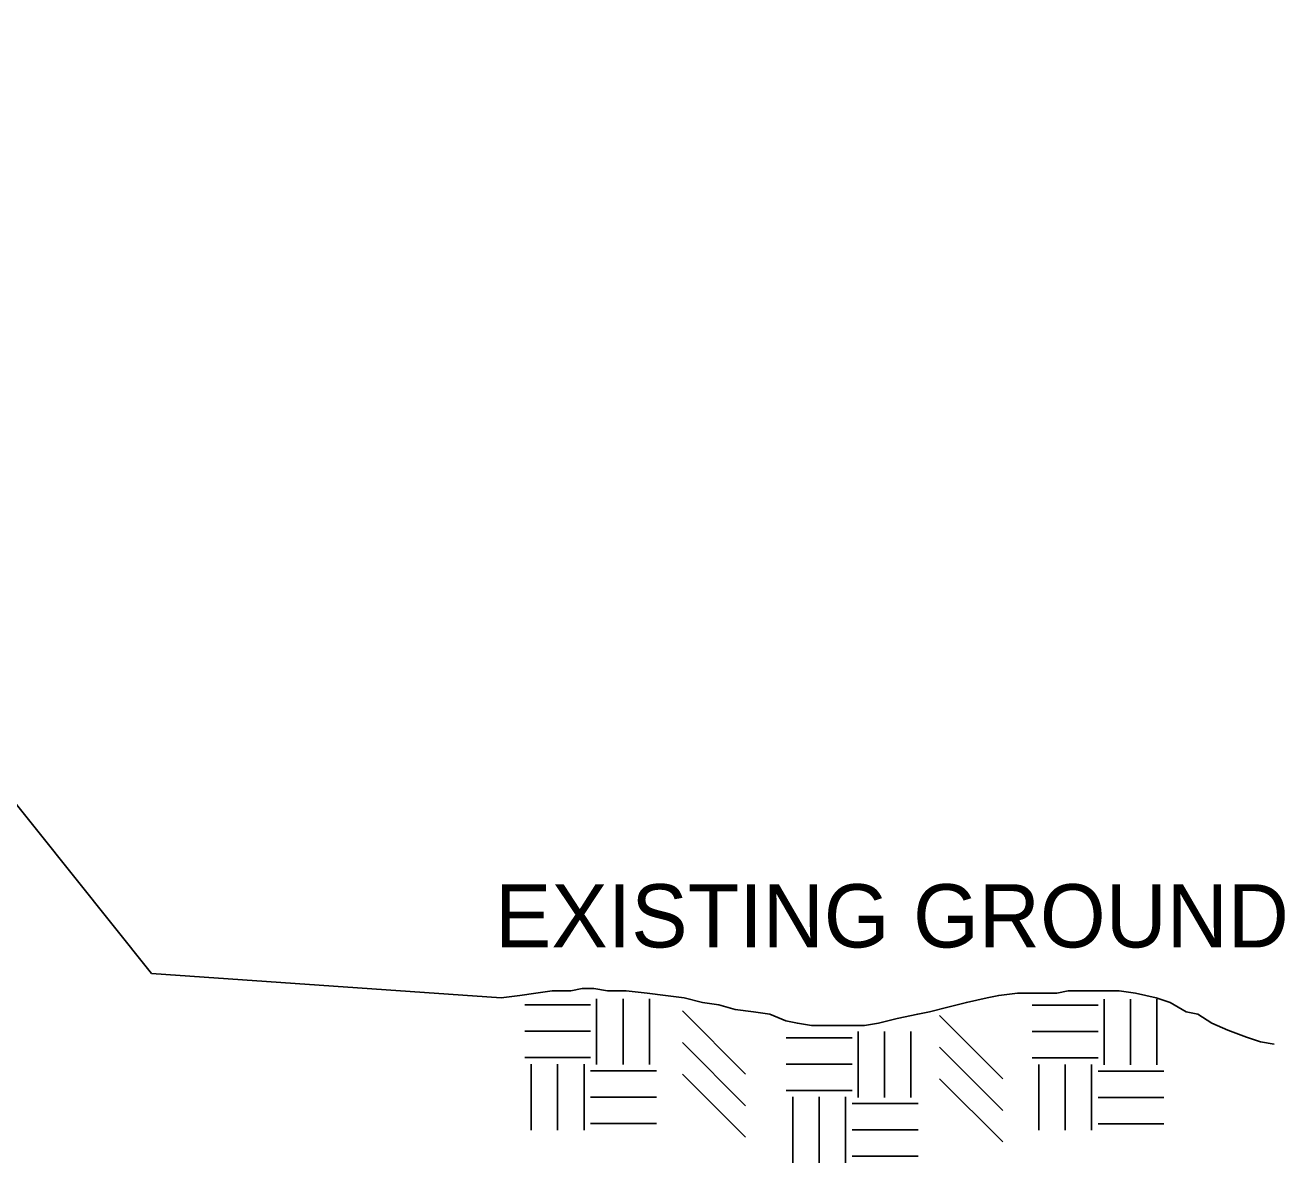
# Model space of a CAD drawing. Extents: x 2003207 to 2014043, y 843846 to 860154.
# Drawn here: x 2013732.03 to 2013751.95, y 844362.61 to 844380.6 of the extents above; entities that cross this region are included whole.
import ezdxf

# ---------------------------------------------------------------- set-up
doc = ezdxf.new("R2010")
doc.units = 0
for name, color, linetype in [('RD_QTY_PermVeg', 7, 'Continuous'), ('RD_TX_TypSect', 7, 'Continuous'), ('RD_XS_ExGround', 7, 'Continuous')]:
    doc.layers.add(name, color=color, linetype=linetype)

msp = doc.modelspace()

# ---------------------------------------------------------------- linework, layer by layer
at = {"layer": 'RD_QTY_PermVeg'}
msp.add_line((2013722.031, 844380.604), (2013734.031, 844365.604), dxfattribs=at)
at = {"layer": 'RD_XS_ExGround'}
for p, q in [((2013734.031, 844365.604), (2013739.562, 844365.218)), ((2013740.975, 844365.106), (2013739.933, 844365.106)), ((2013741.071, 844365.203), (2013741.071, 844364.161)), ((2013741.488, 844365.203), (2013741.488, 844364.161)), ((2013741.905, 844365.203), (2013741.905, 844364.161)), ((2013749.002, 844365.101), (2013747.96, 844365.101)), ((2013749.098, 844365.198), (2013749.098, 844364.156)), ((2013749.515, 844365.198), (2013749.515, 844364.156)), ((2013749.931, 844365.198), (2013749.931, 844364.156)), ((2013743.427, 844364.012), (2013742.427, 844365.012)), ((2013747.495, 844363.938), (2013746.495, 844364.938)), ((2013740.975, 844364.689), (2013739.933, 844364.689)), ((2013745.208, 844364.684), (2013745.208, 844363.642)), ((2013745.624, 844364.684), (2013745.624, 844363.642)), ((2013746.041, 844364.684), (2013746.041, 844363.642)), ((2013749.002, 844364.684), (2013747.96, 844364.684)), ((2013743.427, 844363.512), (2013742.427, 844364.512)), ((2013745.111, 844364.587), (2013744.069, 844364.587)), ((2013747.495, 844363.438), (2013746.495, 844364.438)), ((2013740.975, 844364.272), (2013739.933, 844364.272)), ((2013740.037, 844364.168), (2013740.037, 844363.127)), ((2013740.454, 844364.168), (2013740.454, 844363.127)), ((2013740.871, 844364.168), (2013740.871, 844363.127)), ((2013745.111, 844364.171), (2013744.069, 844364.171)), ((2013749.002, 844364.268), (2013747.96, 844364.268)), ((2013748.064, 844364.164), (2013748.064, 844363.122)), ((2013748.481, 844364.164), (2013748.481, 844363.122)), ((2013748.897, 844364.164), (2013748.897, 844363.122)), ((2013742.016, 844364.064), (2013740.975, 844364.064)), ((2013743.427, 844363.012), (2013742.427, 844364.012)), ((2013747.495, 844362.938), (2013746.495, 844363.938)), ((2013750.043, 844364.059), (2013749.002, 844364.059)), ((2013745.111, 844363.754), (2013744.069, 844363.754)), ((2013742.016, 844363.647), (2013740.975, 844363.647)), ((2013744.174, 844363.65), (2013744.174, 844362.608)), ((2013744.59, 844363.65), (2013744.59, 844362.608)), ((2013745.007, 844363.65), (2013745.007, 844362.608)), ((2013746.153, 844363.546), (2013745.111, 844363.546)), ((2013750.043, 844363.643), (2013749.002, 844363.643)), ((2013742.016, 844363.231), (2013740.975, 844363.231)), ((2013746.153, 844363.129), (2013745.111, 844363.129)), ((2013750.043, 844363.226), (2013749.002, 844363.226)), ((2013746.153, 844362.712), (2013745.111, 844362.712))]:
    msp.add_line(p, q, dxfattribs=at)
msp.add_lwpolyline([(2013751.787, 844364.486), (2013751.568, 844364.522), (2013751.348, 844364.596), (2013751.055, 844364.705), (2013750.799, 844364.815), (2013750.579, 844364.962), (2013750.396, 844364.998), (2013750.14, 844365.145), (2013749.92, 844365.218), (2013749.591, 844365.291), (2013749.335, 844365.328), (2013749.042, 844365.328), (2013748.713, 844365.328), (2013748.53, 844365.328), (2013748.346, 844365.291), (2013748.127, 844365.291), (2013747.907, 844365.291), (2013747.724, 844365.291), (2013747.431, 844365.255), (2013747.248, 844365.218), (2013746.919, 844365.145), (2013746.626, 844365.072), (2013746.333, 844364.998), (2013746.15, 844364.962), (2013745.821, 844364.889), (2013745.528, 844364.815), (2013745.308, 844364.779), (2013745.125, 844364.779), (2013744.906, 844364.779), (2013744.686, 844364.779), (2013744.466, 844364.779), (2013744.247, 844364.815), (2013744.064, 844364.852), (2013743.808, 844364.962), (2013743.551, 844364.998), (2013743.259, 844365.035), (2013743.002, 844365.108), (2013742.746, 844365.145), (2013742.453, 844365.218), (2013742.16, 844365.255), (2013741.868, 844365.291), (2013741.538, 844365.328), (2013741.245, 844365.328), (2013741.026, 844365.365), (2013740.843, 844365.365), (2013740.66, 844365.328), (2013740.367, 844365.328), (2013740.111, 844365.291), (2013739.854, 844365.255), (2013739.562, 844365.218)], dxfattribs=at)

# ---------------------------------------------------------------- texts
at = {"layer": 'RD_TX_TypSect'}
msp.add_text('EXISTING GROUND', height=1, dxfattribs=at).set_placement((2013739.462, 844366.015))

doc.saveas('drawing.dxf')
